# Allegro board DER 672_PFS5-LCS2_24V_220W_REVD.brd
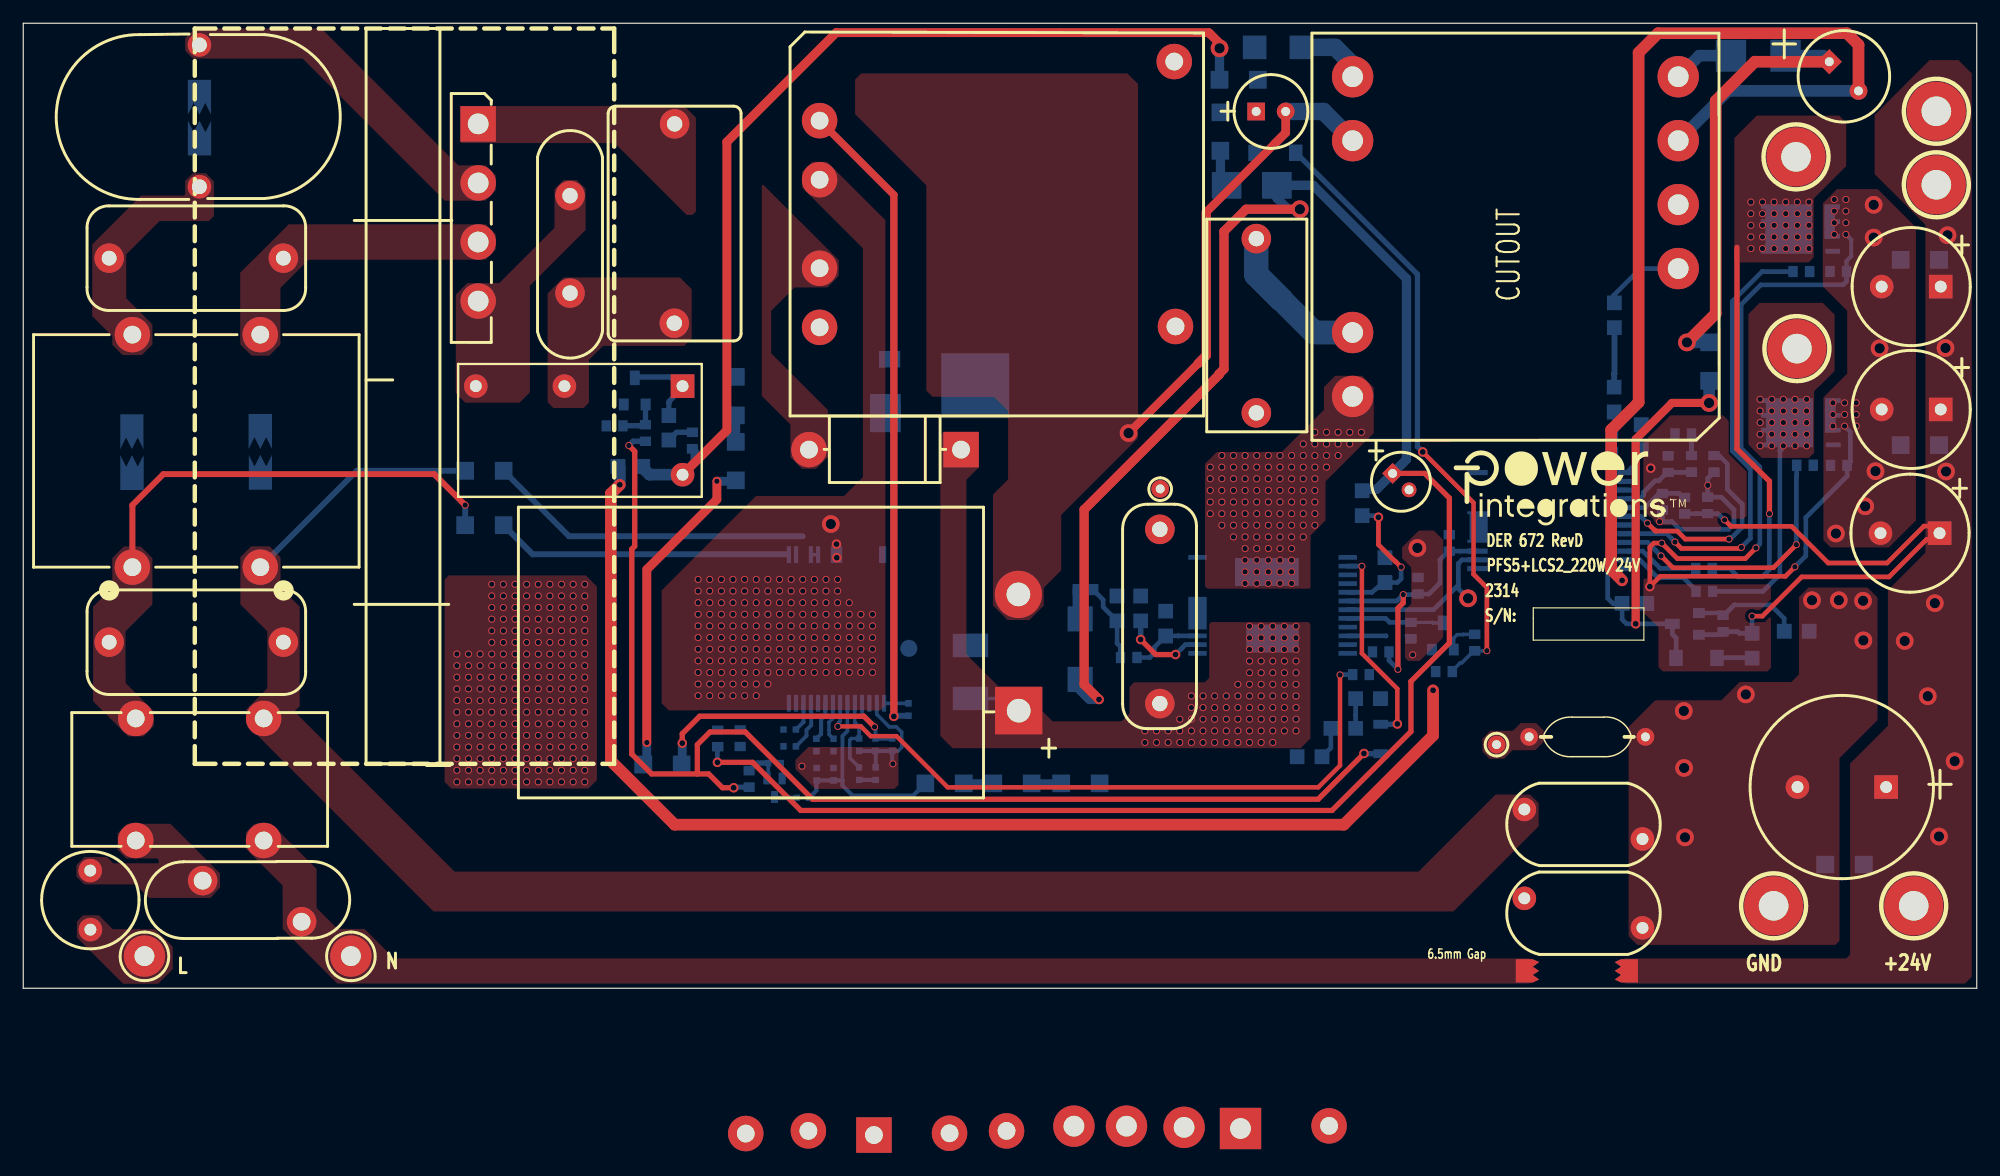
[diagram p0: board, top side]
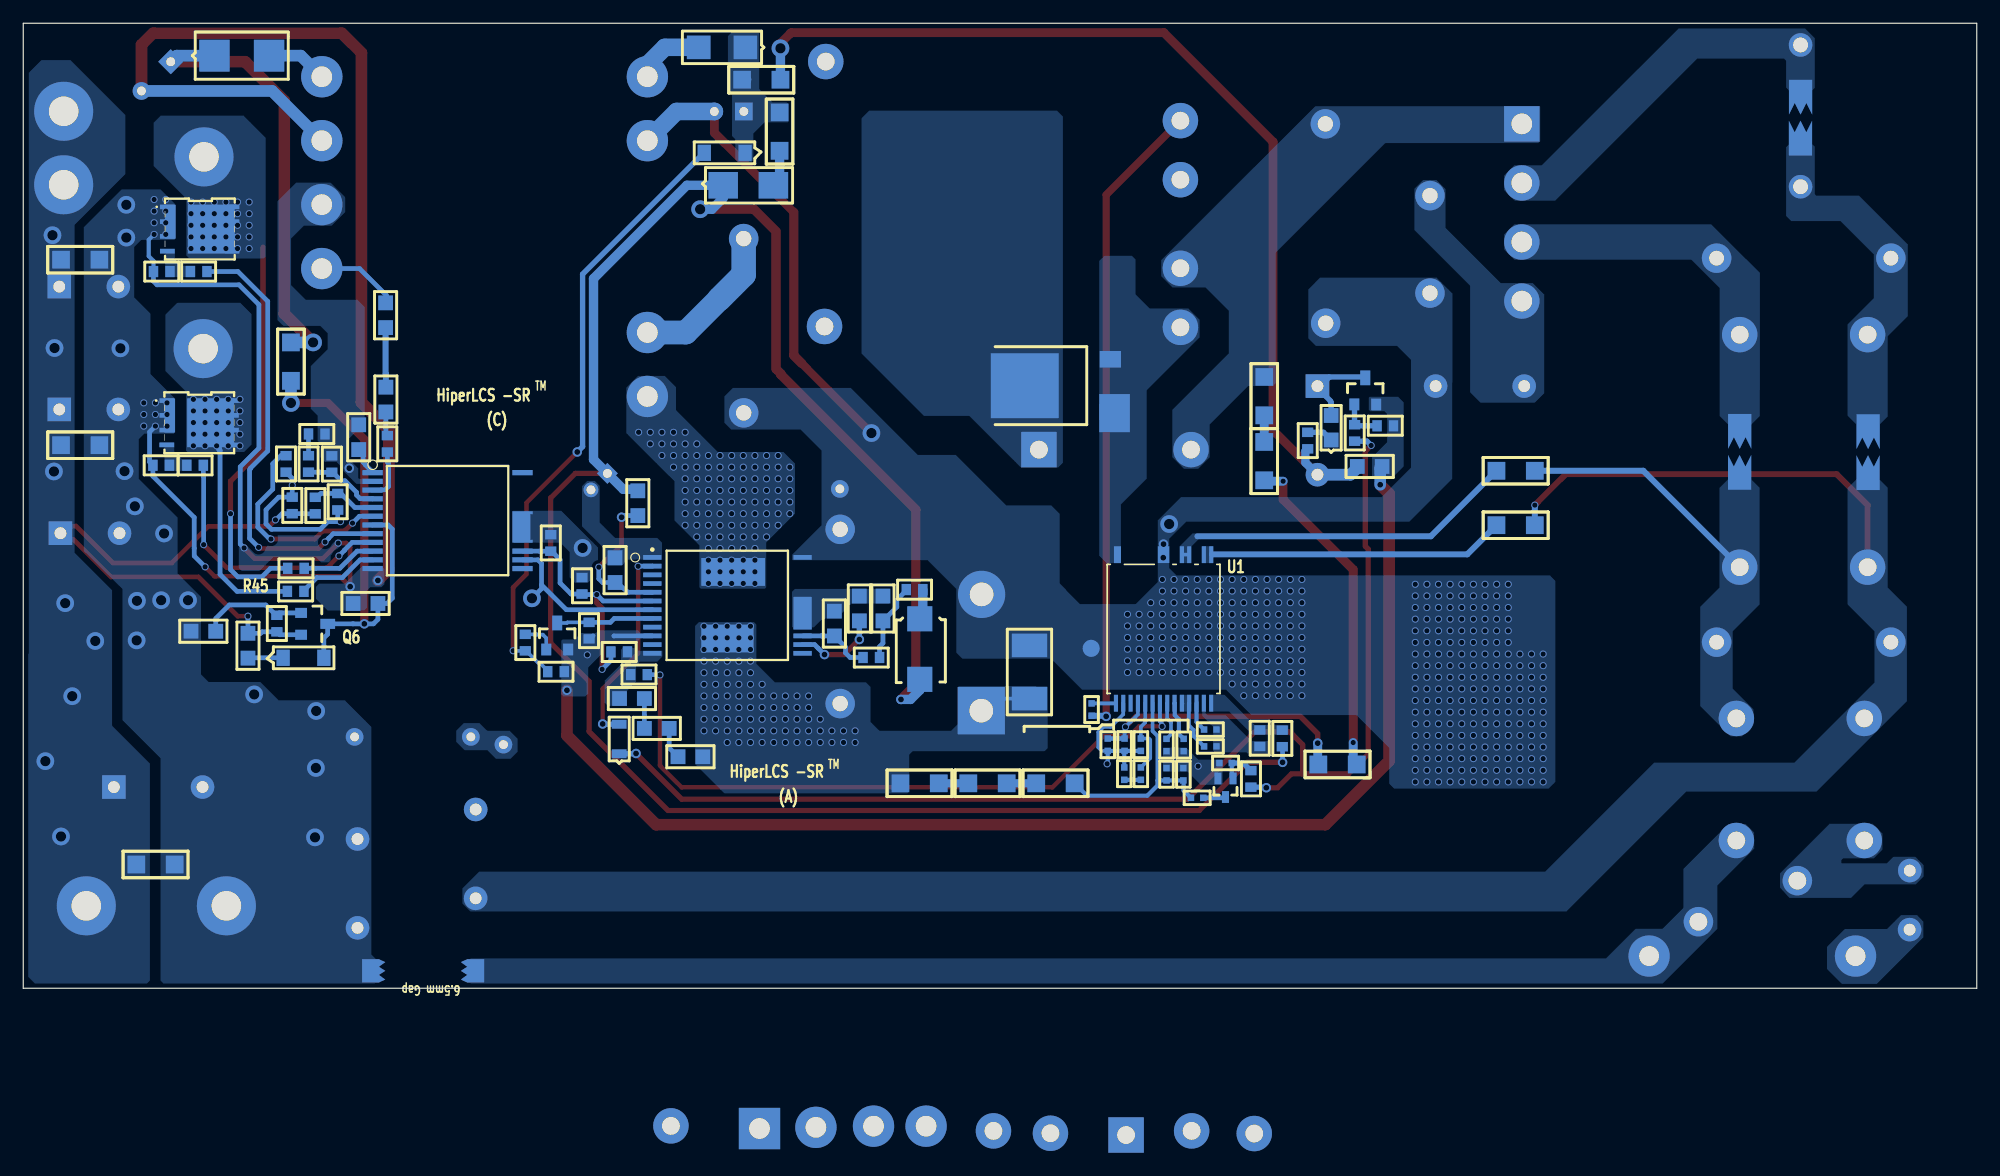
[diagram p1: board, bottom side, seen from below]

Outline 168 x 83 mm; copper layers: TOP, BOTTOM. Coordinates in mm from the lower left corner of the outline.
Outline path: 0,83 168,83 168,0 0,0 0,83

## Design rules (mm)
constraint set DEFAULT: min track width 0.305

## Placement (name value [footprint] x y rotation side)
+24V1  Hole_100mils  [PI_HOLE_100MIL]  162.58 7.09 0 top
BR1  GBU8K-BP  [PIDAXBRIDGEGBU8]  39.12 74.35 270 top
C1  0.33 uF  [PI_NP_CAPRAD709X354LS590D050]  7.39 62.8 0 top
C2  0.33 uF  [PI_NP_CAPRAD709X354LS590D050]  7.39 29.77 0 top
C3  470 nF  [PINPCAPRAD760X450675040]  56.02 74.35 270 top
C5  10 uF  [PISMC0805]  53.28 44.88 180 bottom
C7  1 uF  [PISMC0603]  61.65 22.22 270 bottom
C8  2.2 uF  [PISMC0402]  66.45 22.25 180 bottom
C9  2.2 uF  [PISMC0402]  66.45 20.8 180 bottom
C10  220 uF  [PIPOLCAPCLYD25MM10MMLS080]  85.58 23.88 90 top
C11  10 nF  [PISMC1812]  81.47 24.91 90 bottom
C12  470 pF  [PISMR0402]  74.73 21.48 270 bottom
C14  470 pF  [PISMR0402]  69.68 17.87 90 bottom
C15  100 nF  [PISMR0402]  71.89 21.48 270 bottom
C16  1 uF  [PISMR0402]  73.31 17.93 90 bottom
C17  1 uF  [PISMC0805]  98.24 32.43 270 bottom
C18  10 uF  [PISMC0805]  94.07 31.6 90 bottom
C19  220 nF  [PISMC0805]  96.1 31.6 90 bottom
C20  68 nF  [PINPCAPRAD760X250590040]  97.75 24.48 90 top
C21  47 uF  [PIPOLCAPCLYD200LS80030]  117.76 44.28 315 top
C22  1 uF  [PISMC0805]  117.1 34.9 90 bottom
C23  100 uF  [PIPOLCAPCYLD250LS100030]  106.03 75.41 0 top
C24  1 uF  [PISMC0603]  119.95 33.91 90 bottom
C25  22 nF  [PINPXCAPRAD720X340590040]  106.05 64.48 270 top
C26  3.3 nF  [PINPYCAPRAD540X290LS400040]  129.09 15.38 0 top
C27  330 uF  [PIPOLCAPCYLD400LS200040]  164.9 60.35 180 top
C28  330 uF  [PIPOLCAPCYLD400LS200040]  164.9 49.78 180 top
C29  100 nF  [PISMC0603]  144.87 40.82 90 bottom
C30  10 uF  [PISMC1206]  164.75 46.71 180 bottom
C31  330 uF  [PIPOLCAPCYLD400LS200040]  164.8 39.14 180 top
C32  10 uF  [PISMC1206]  164.75 62.66 180 bottom
C33  10 uF  [PISMC0805]  139.63 33.1 180 bottom
C34  100 uF  [PIPOLCAPCLYD320LS140030]  155.32 79.69 315 top
C35  100 pF  [PISMC0603]  141.46 44.37 90 bottom
C36  2.2 nF  [PISMC0603]  143.47 47.67 180 bottom
C37  470 pF  [PISMC0805]  136.84 56.82 90 bottom
C38  100 nF  [PISMC0603]  122.64 37.59 90 bottom
C39  10 uF  [PISMC0805]  139.15 46.33 90 bottom
C40  2.2 uF  [PISMC0805]  153.58 30.71 180 bottom
C41  3.3 nF  [PINPYCAPRAD540X290LS400040]  129.09 7.74 0 top
C42  150 pF  [PINPCAPRAD6P5X5P5X10MMLSD030]  139.51 21.62 180 top
C43  1800 uF  [PIPOLCAPCLYD630LS300040]  160.2 17.31 180 top
C44  10 uF  [PISMC1206]  158.28 10.65 180 bottom
D1  1N5408G  [PIDV300X200X060DO15D0201AD]  83.95 46.33 180 top
D2  BAS416,115  [PISMDSOD323]  55.52 47.16 90 bottom
D3  VS-5EWH06FNTR-M3  [PI_SM_TO252_DPAK]  74.51 49.61 0 bottom
D4  MURS160T3G  [PISMSMB]  90.9 31.78 270 bottom
D5  ES1A-13-F  [PISMDO214AC12]  107.81 69.06 180 bottom
D6  US1D  [PISMDSMA]  105.9 80.93 0 bottom
D7  B180B-13-F  [PISMDO214AA12]  151.56 80.21 180 bottom
D9  BAV16WS-7-F  [PISMSOD323]  116.75 20.17 90 bottom
F1  5 A  [PI_TR5_SUBMIN_FUSE]  5.78 5.04 90.2 top
FL1  Hole_100mils  [PI_HOLE_100MIL]  152.53 55.02 0 top
FL2  Hole_100mils  [PI_HOLE_100MIL]  152.46 71.51 0 top
FL3  Hole_100mils  [PI_HOLE_100MIL]  164.53 75.43 0 top
FL4  Hole_100mils  [PI_HOLE_100MIL]  164.53 69.11 0 top
FL5  Hole_30mils  [PI_HOLE_30MIL]  97.77 42.95 0 top
FL6  Hole_30mils  [PI_HOLE_30MIL]  126.7 20.95 0 top
GND1  Hole_100mils  [PI_HOLE_100MIL]  150.53 7.09 0 top
L2  20 mH  [PI4P28X19P5X20LSD60]  14.89 46.22 90 top
L3  2.3 mH  [PI4P21P7X11P5D60]  15.17 17.96 90 top
L4  330 uH  [PI_TOROID_2P_550X950_LS480_D050]  15.15 81.13 270 top
LINE  WHT  [PITPKEYSTONE125X125]  10.42 2.77 0 top
NEUTRAL  YEL  [PITPKEYSTONE125X125]  28.18 2.77 0 top
NOREF  -  []  0 0 90 top
NOREF#2  -  []  29.48 19.3 0 top
NOREF#3  -  []  123.02 46.23 0 top
NOREF#4  -  []  0 0 0 top
NOREF#5  -  []  -101.34 71.35 0 top
NOREF#6  -  []  -109.61 -185.23 0 top
Q1  DMN10H700S-7  [PISMSOT23123_1]  51.65 50.22 180 bottom
Q2  RJU003N03T106  [PISMSOT323]  65.26 18.05 0 bottom
Q3  MMBTA06LT1  [PISMSOT23123_1]  121.14 29.13 180 bottom
Q4  AONS66614  [PISMPQFN5X6B]  155.61 67.21 270 bottom
Q5  AONS66614  [PISMPQFN5X6B]  155.66 50.55 270 bottom
Q6  FMMT591  [PISMSOT23123_1]  144.1 30.4 270 bottom
R1  75.0 k  [PISMR1206]  41.31 44.51 180 bottom
R2  75.0 k  [PISMR1206]  41.31 39.83 180 bottom
R3  10  [PISMR0603]  57.54 46.39 90 bottom
R4  10  [PISMR0603]  53.5 47.05 90 bottom
R5  10 k  [PISMR0603]  146.19 32.08 270 bottom
R6  6.2 M  [PISMR1206]  61.27 49.28 90 bottom
R8  6.2 M  [PISMR1206]  61.27 43.69 90 bottom
R9  10  [PISMR0603]  59.73 20.78 90 bottom
R10  10.0 k  [PISMR0402]  76.12 23.44 90 bottom
R11  3.74 M  [PISMR1206]  53.32 19.25 0 bottom
R12  3.74 M  [PISMR1206]  92.57 17.63 180 bottom
R13  6.2 M  [PISMR1206]  86.73 17.63 180 bottom
R14  6.2 M  [PISMR1206]  77.58 17.63 0 bottom
R15  165.0 k  [PISMR0402]  73.29 21.48 270 bottom
R16  280.0 k  [PISMR0402]  69.68 20.39 90 bottom
R17  0.0  [PISMR0402]  68.21 20.39 90 bottom
R18  806.0 k  [PISMR0402]  66.51 16.38 0 bottom
R19  30.1 k  [PISMR0402]  71.89 18.99 270 bottom
R20  196.0 k  [PISMR0402]  68.23 18.94 270 bottom
R21  10  [PISMR0603]  62.42 17.3 90 bottom
R22  10  [PISMR0603]  95.78 28.45 180 bottom
R23  2.2  [PISMR0603]  92.06 34.29 180 bottom
R24  2 M  [PISMR0805]  109.56 19.91 0 bottom
R25  1.8 M  [PISMR0805]  112.45 22.35 0 bottom
R26  200 k  [PISMR0805]  114.59 24.92 0 bottom
R27  22.6 k  [PISMR0603]  114.34 26.97 0 bottom
R28  20 k  [PISMR0603]  117.46 28.93 180 bottom
R30  2.2  [PISMR0805]  115.15 40.65 90 bottom
R31  750  [PISMR1206]  102.96 72.03 90 bottom
R32  47 k  [PISMR0603]  124.83 29.02 90 bottom
R33  158 k  [PISMR0603]  119.34 31.47 270 bottom
R34  100  [PISMR0603]  122.89 27.23 180 bottom
R35  200  [PISMR0805]  148.68 30.53 270 bottom
R36  133 k  [PISMR0603]  142.89 40.8 90 bottom
R37  24.3 k  [PISMR0603]  140.95 42.56 270 bottom
R38  10 k  [PISMR0603]  156.8 61.65 180 bottom
R39  4.7  [PISMR0603]  153.63 61.65 180 bottom
R40  499  [PISMR0603]  145.26 36.12 180 bottom
R41  10  [PISMR1206]  144.98 52.25 90 bottom
R42  10 k  [PISMR0603]  156.85 44.98 180 bottom
R43  4.7  [PISMR0603]  153.93 44.98 180 bottom
R44  150 k  [PISMR0603]  143.47 44.39 90 bottom
R45  499  [PISMR0603]  145.28 34.14 180 bottom
R48  274 k  [PISMR0603]  136.69 47.54 270 bottom
R49  750 k  [PISMR0805]  136.81 49.57 90 bottom
R50  75 k  [PISMR0603]  145.4 45.81 270 bottom
R51  10  [PISMR1206]  106.18 78.14 180 bottom
R53  10 k  [PISMR0603]  50.15 48.38 0 bottom
R54  10 K  [PISMR0402]  64.07 19.37 0 bottom
RL1  SPST NO  [PI_RELAY1]  56.7 51.79 180 top
RT1  10  [PI_RAD770X220LS330D052]  47.02 68.17 270 top
RV1  320 Vac  [PIDISC675X225LS335X140040]  15.43 9.25 0 top
SG1  6.5mm gap  [PI_SPARK_GAP_6P5MM]  133.61 1.5 0 top
SG2  6.5mm gap  [PI_SPARK_GAP_6P5MM]  133.61 1.5 0 bottom
T1  PQ32/20  [PI_BOBBIN_BPQ32_20_12P]  68.49 79.7 0 top
T2  ETD34  [PI_BOBBIN_ETD34_12P_CUTOUT]  142.35 50.88 180 top
U1  PFGCZ  [INSOP-T28F]  69.93 30.9 90 bottom
U2  LCS7265C  [PI_IC_INSOP_24C_1]  107.44 32.93 180 bottom
U3  LSR2000C-H007  [PI_IC_INSOP_24D]  137.95 44.35 180 bottom
VR1  MMSZ5256B-7-F  [PI_SM_SOD-123_12]  105.93 71.86 0 bottom
VR2  MMSZ5245B-7-F  [PI_SM_SOD-123_12]  145.65 28.42 180 bottom

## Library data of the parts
+24V1 FL1-FL4 GND1 = FlyingLead: room: 2
BR1 = DISCRETE BRIDGE_+~~-: alternate symbols: (pidaxbridgegbu8_horz)
C1-C3 C11 C17 C19 C20 C25 C29 C38 C42 = CAP NP
C5 C18 C33 = CAP NP: alternate symbols: (Unisem_RMCF0805UL,CC0805,pismc0805_1)
C7 C35-C37 C40 = CAP NP: room: 2
C8 C9 C12 C14-C16 = CAP NP: alternate symbols: (pismr0402_1); room: 2
C10 = CAP POL: alternate symbols: (pipcap25h40x10mmls080H)
C21 = CAP POL: alternate symbols: (pipolcapclyd200ls80030h)
C22 C24 = CAP NP: room: 1
C23 = CAP POL: alternate symbols: (pipolcapclyd250ls100d30h590)
C26 C41 = CAP NP: alternate symbols: (pinpycaprad540x290ls400040h)
C27 C28 C31 = CAP POL
C30 C32 C44 = CAP NP: alternate symbols: (pismc1206_1)
C34 = CAP POL: alternate symbols: (pipolcapclyd320ls140030430h)
C39 = CAP NP: alternate symbols: (Unisem_RMCF0805UL)
C43 = CAP POL: alternate symbols: (pipolcapclyd630ls3000401000h)
D1 = DIODE: alternate symbols: (pidv300x472x060do14wbead,pidax800x225060do15do201ad,pidv300x200x060do14wbead)
D2 D5 D6 = DIODE
D3 = DIODE_DPAK
D4 D9 = DIODE: room: 1
D7 = DIODE SCHOTTKY
F1 = FUSE
FL5 FL6 = FlyingLead
L2 L3 = TORRID 4P_14_23
L4 = INDUCTOR
LINE NEUTRAL = TESTPOINT
Q1 = FET_N_GSD
Q2 = FET_N_SGD
Q3 = NPN_BEC
Q4 Q5 = FET_N_SGD_123_4_5678
Q6 = PNP_BEC
R1 R2 R22 R23 R30-R32 R34 R39-R41 R43 R45 R51 = R
R3-R6 R8 R9 R11-R21 R36-R38 R42 R44 R48-R50 R53 R54 = R: room: 2
R10 = R: alternate symbols: (pismr0402_1); room: 2
R24 R25 R27 R28 R33 = R: room: 1
R26 = R: alternate symbols: (Unisem_RMCF0805UL)
R35 = R: alternate symbols: (pismr0805_1)
RL1 = RELAY SPST_NO_1634
RT1 = THERMISTOR
RV1 = VARISTOR
SG1 SG2 = SPARK_GAP
T1 = BPQ32/20_12P/GENERIC
T2 = BETD34_12P/GENERIC
U1 = PFSGaN_InSOP-T28F28: User Part Number: PN; Tolerance: TOL
U2 = HiperLCS-SR_A_INSOP24C_5
U3 = HiperLCS2-SR
VR1 VR2 = DIODE_ZENER

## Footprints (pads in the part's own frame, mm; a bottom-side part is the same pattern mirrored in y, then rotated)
INSOP-T28F
  rect 1.448x0.356 smd: 1(-6.388,4.095) 2(-6.388,3.465) 3(-6.388,2.835) 4(-6.388,2.205) 5(-6.388,1.575) 6(-6.388,0.945) 7(-6.388,0.315) 8(-6.388,-0.315) 9(-6.388,-0.945) 10(-6.388,-1.575) 11(-6.388,-2.205) 12(-6.388,-2.835) 13(-6.388,-3.465) 14(-6.388,-4.095) 15(6.388,-4.095) 16(6.388,-3.465) 18(6.388,-2.205) 19(6.388,-1.575)
  rect 1.448x0.986 smd: 21(6.388,0)
  rect 1.448x0.61 smd: 28(6.388,3.968)
PI4P21P7X11P5D60
  round 3.048 hole 1.524: 1(-5.25,5.5) 2(-5.25,-5.5) 3(5.25,-5.5) 4(5.25,5.5)
PI4P28X19P5X20LSD60
  round 3.048 hole 1.524: 1(-10,-5.5) 2(-10,5.5) 3(10,5.5) 4(10,-5.5)
PI_BOBBIN_BPQ32_20_12P
  rect 3.048x3.048 hole 1.524: 1(4.674,-92.329)
  round 3.048 hole 1.524: 2(0,-5.08) 3(0,-10.16) 4(0,-17.78) 5(0,-22.86) 6(-0.965,-91.973) 7(-6.35,-92.202) 8(30.607,-22.784) 9(11.176,-92.177) 10(16.078,-91.973) 11(43.815,-91.542) 12(30.5,0)
PI_BOBBIN_ETD34_12P_CUTOUT
  rect 3.556x3.556 hole 1.778: 1(37.668,62.941)
  round 3.556 hole 1.778: 2(42.52,62.84) 3(0.025,-11.025) 4(0.025,-16.525) 5(0.025,-22.025) 6(0.025,-27.525) 7(28.025,-27.525) 8(28.025,-22.025) 9(51.994,62.738) 10(47.473,62.738) 11(28.025,-5.525) 12(28.025,-0.025)
PI_HOLE_30MIL
  round 1.524 hole 0.762: 1(0,0)
PI_HOLE_100MIL
  round 5.08 hole 2.54: 1(0,0)
PI_IC_INSOP_24C_1
  rect 1.58x0.41 smd: 1(-6.46,4.125) 2(-6.46,3.375) 3(-6.46,2.625) 4(-6.46,1.875) 5(-6.46,1.125) 6(-6.46,0.375) 7(-6.46,-0.375) 8(-6.46,-1.125) 9(-6.46,-1.875) 10(-6.46,-2.625) 11(-6.46,-3.375) 12(-6.46,-4.125) 13(6.46,-4.125) 14(6.46,-3.375) 15(6.46,-2.625) 24(6.46,4.125)
  rect 1.58x2.81 smd: 16(6.46,-0.675)
  rect 5.49x2.4 smd: 19(0.495,2.875)
  rect 4.5x2.4 smd: 25(0,-2.85)
PI_IC_INSOP_24D
  rect 1.75x0.45 smd: 1(0,0) 2(0,-0.75) 3(0,-1.5) 4(0,-2.25) 5(0,-3) 6(0,-3.75) 7(0,-4.5) 8(0,-5.25) 9(0,-6) 10(0,-6.75) 11(0,-7.5) 12(0,-8.25) 13(12.89,-8.25) 14(12.89,-7.5) 15(12.89,-6.75) 24(12.89,0)
  custom 0.438x0.438 smd: 16(12.89,-4.67)
PI_NP_CAPRAD709X354LS590D050
  round 2.54 hole 1.27: 1(0,0) 2(14.986,0)
PI_RAD770X220LS330D052
  round 2.54 hole 1.321: 1(0,0) 2(8.382,0)
PI_RELAY1
  rect 2.032x2.032 hole 1.016: 1(0,0)
  round 2.032 hole 1.016: 3(10.16,0) 4(17.78,0) 6(0,7.62)
PI_SM_SOD-123_12
  rect 1.143x1.397 smd: 1(0,0) 2(3.505,0)
PI_SM_TO252_DPAK
  rect 1.829x1.422 smd: 1(0,0) 3(0,-4.445)
  rect 5.842x5.588 smd: 2(7.62,-2.223)
PI_SPARK_GAP_6P5MM
  custom 0.5x0.5 smd: 1(-4.25,0) 2(4.25,0)
PI_TOROID_2P_550X950_LS480_D050
  round 2.032 hole 1.27: 1(0,0) 2(12.192,0)
PI_TR5_SUBMIN_FUSE
  round 2.032 hole 1.016: 1(0,0) 2(5.08,0)
PIDAXBRIDGEGBU8
  rect 3.048x3.048 hole 1.778: 1(0,0)
  round 3.048 hole 1.778: 2(5.08,0) 3(10.16,0) 4(15.24,0)
PIDISC675X225LS335X140040
  round 2.54 hole 1.524: 1(0,0) 2(8.509,-3.531)
PIDV300X200X060DO15D0201AD
  rect 3.048x3.048 hole 1.524: 1(3.302,0)
  round 3.048 hole 1.524: 2(16.383,0)
PINPCAPRAD6P5X5P5X10MMLSD030
  round 1.524 hole 0.762: 1(0,0) 2(10,0)
PINPCAPRAD760X250590040
  round 2.54 hole 1.321: 1(0,0) 2(14.986,0)
PINPCAPRAD760X450675040
  round 2.54 hole 1.321: 1(0,0) 2(17.145,-0.025)
PINPXCAPRAD720X340590040
  round 2.54 hole 1.321: 1(0,0) 2(14.986,0)
PINPYCAPRAD540X290LS400040
  round 2.032 hole 1.016: 1(0,0) 2(10.16,-2.54)
PIPOLCAPCLYD25MM10MMLS080
  rect 4.064x4.064 hole 2.032: 1(0,-0.025)
  round 4.064 hole 2.032: 2(10,0)
PIPOLCAPCLYD200LS80030
  rect 1.27x1.27 hole 0.762: 1(0,0)
  round 1.27 hole 0.762: 2(2,0)
PIPOLCAPCLYD320LS140030
  rect 1.524x1.524 hole 0.762: 1(0,0)
  round 1.524 hole 0.762: 2(3.556,0)
PIPOLCAPCLYD630LS300040
  rect 2.032x2.032 hole 1.016: 1(0,0)
  round 2.032 hole 1.016: 2(7.62,0)
PIPOLCAPCYLD250LS100030
  rect 1.524x1.524 hole 0.762: 1(0,0)
  round 1.524 hole 0.762: 2(2.54,0)
PIPOLCAPCYLD400LS200040
  rect 2.032x2.032 hole 1.016: 1(0,0)
  round 2.032 hole 1.016: 2(5.08,0)
PISMC0402
  rect 0.559x0.559 smd: 1(0,0) 2(1.067,0)
PISMC0603
  rect 0.813x0.965 smd: 1(0,0) 2(1.422,0)
PISMC0805
  rect 1.27x1.27 smd: 1(0,0) 2(2.134,0)
PISMC1206
  rect 1.524x1.524 smd: 1(0,0) 2(3.302,0)
PISMC1812
  rect 2.032x3.048 smd: 1(0,0) 2(4.572,0)
PISMDO214AA12
  rect 2.616x2.743 smd: 1(0,0) 2(4.699,0)
PISMDO214AC12
  rect 2.54x2.286 smd: 1(0,0) 2(4.318,0)
PISMDSMA
  rect 2.032x2.032 smd: 1(0,0) 2(4.013,0)
PISMDSOD323
  rect 1.27x1.27 smd: 1(0,0) 2(2.108,0)
PISMPQFN5X6B
  rect 0.406x1.27 smd: 1(0,0) 2(1.27,0) 3(2.54,0) 4(3.81,0)
  rect 0.406x1.219 smd: 5(3.81,5.588) 6(2.54,5.588) 7(1.27,5.588) 8(0,5.588)
PISMR0402
  rect 0.559x0.559 smd: 1(0,0) 2(1.067,0)
PISMR0603
  rect 0.813x0.965 smd: 1(0,0) 2(1.422,0)
PISMR0805
  rect 1.27x1.27 smd: 1(0,0) 2(2.134,0)
PISMR1206
  rect 1.524x1.524 smd: 1(0,0) 2(3.302,0)
PISMSMB
  rect 2.159x2.159 smd: 1(0,0) 2(5.207,0)
PISMSOD323
  rect 0.762x1.27 smd: 1(0,0) 2(2.54,0)
PISMSOT323
  rect 0.61x1.016 smd: 1(0,0) 2(-1.3,0) 3(-0.65,1.6)
PISMSOT23123_1
  rect 0.864x1.016 smd: 1(-1.88,0) 2(0,0)
  rect 0.864x1.27 smd: 3(-0.94,2.286)
PITPKEYSTONE125X125
  round 3.556 hole 1.702: 1(0,0)

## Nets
5VL: C24.1 C38.1 R28.1 U2.6 U3.15
+24V: +24V1.1 C27.1 C28.1 C29.1 C30.1 C31.1 C32.1 C43.1 C44.1 FL3.1 FL4.1 Q6.2(EMITTER) R5.2 R35.1 R36.1 SG1.2
GND: C26.2 C27.2 C28.2 C30.2 C31.2 C32.2 C33.1 C34.2 C40.1 C41.2 C42.1 C43.2 C44.2 GND1.1 Q4.1 Q4.2 Q4.3(S3) Q5.1 Q5.2 Q5.3(S3) R38.1 R42.1 SG2.2 T2.5 U3.12
VCC: C7.1 R9.2 U1.14
BM: D9.1 R4.1 R21.1
BPS: D7.2 T2.6
C: C15.1 R19.1 U1.5
D1: R2.1 U1.15 U1.16
D2: R1.1 U1.18 U1.19
FB: C14.1 R14.1 R18.2 R20.2 U1.6
FL: U2.7 U3.14
G2: C7.2 C8.2 C9.2 U1.13
GP: C5.2 C24.2 C38.2 Q1.2(S) Q3.2(EMITTER) R33.2 R34.2 R53.1 U2.10 U3.16
GSB: C29.2 C35.2 C36.2 C39.2 R37.2 R50.2 T2.4 U3.2
IS: C37.2 T2.3
L: D3.3 T1.5 U1.28
LINE1: F1.2 L3.1 RV1.1
NEUTRAL1: L3.2 NEUTRAL.1 RV1.2 SG1.1 SG2.1
OVP: R32.1 R34.1 VR1.2
PFC_VCC: C21.1 D4.2 D5.1 R9.1 R30.2
PGOOD: R27.1 U1.7
PGT: R16.2 U1.8
PS: R17.2 U1.9
REF: C9.1 U1.10 U1.11
RELAY_VCC: C5.1 R3.1 R51.2 RL1.6
RTN: C3.2 C10.2 C11.2 C20.2 C23.2 C25.2 FL5.1 RL1.3 RT1.2 T1.3 T2.8 U1.21 U2.24
TO: U1.3
V: C12.1 R11.2 R15.1 U1.4
VBULK: C10.1 C11.1 C20.1 D1.1 D3.2 R12.1 R24.1 U2.25
VDR: C8.1 U1.12
VRECT: BR1.1 C3.1 D1.2 R6.2 T1.4
VS: R10.1 T1.2
VSC: R10.2 U1.1
Y1: C2.2 C26.1 L2.1 L3.3 R1.2
Y2: C2.1 C41.1 L2.2 L3.4 R2.2
N4285050: C17.1 C18.2 C19.2 U2.16
N4286456: C19.1 U2.14
N4286477: C17.2 R22.1 U2.15
N4286493: D4.1 R23.2
N4298336: D6.2 T2.7
N4342721: C23.1 D6.1 R31.2 R51.1 VR1.1
N4344251: Q3.3 R33.1 U2.8
N4345605: C21.2 C22.2 U2.1
N4347891: C22.1 R30.1 U2.5
N4369156: R36.2 R37.1 U3.5
N4369530: C35.1 R44.1 U3.4
N4369660: R48.2 U3.3
N4369788: C39.1 U3.1
N4383576: R43.2 U3.9
N4398139: FL2.1 Q4.5 Q4.6 Q4.7 Q4.8 R40.1
N4399978: FL1.1 Q5.5 Q5.6 Q5.7 Q5.8 R45.1
N4403558: Q4.4 R38.2 R39.1
N4403571: R39.2 U3.8
N4411199: R48.1 R49.1
N4411203: C37.1 R49.2
N4415619: C36.1 R44.2
N4433947: Q5.4 R42.2 R43.1
N4462598: C33.2 Q6.3 R41.1 U3.7 VR2.2
N4490514: C25.1 T2.11
N4535120: R26.2 R27.2 R28.2 U2.12
N4541248: U2.3
N11926581: R50.1 U3.6(PS)
N12003586: Q3.1 R32.2
N12130188: R45.2 U3.11
N12130239: R40.2 U3.10
N12141521: T2.12 U2.19
N12150808: C18.1 R22.2 R23.1
N12190763: C34.1 D7.1 R41.2
N12204254: C1.1 L2.3 L4.2
N12204278: BR1.2 L4.1
N12204372: BR1.4 RL1.4(NO) RT1.1
N12204532: BR1.3(AC2) C1.2 L2.4
N12221428: R6.1 R8.2
N12221554: R8.1 R11.1
N12221692: R12.2 R13.1
N12221812: R13.2 R14.2
N12221868: C12.2 C14.2 C15.2 C16.2 Q2.1(S) R15.2 R16.1 R17.1 R20.1 R54.2 U1.2
N12222300: C16.1 R19.2
N12229995: D5.2 R31.1
N12233962: Q2.3 R18.1
N12234276: Q2.2 R21.2 R54.1
N12240068: Q1.1 R4.2 R53.2
N12240080: D2.2 Q1.3 RL1.1
N12240868: D2.1 R3.2
N12267959: C40.2 Q6.1 R5.1
N12332190: R24.2 R25.1
N12332212: R25.2 R26.1
N12355111: R35.2 VR2.1
N12387180: F1.1 LINE.1
N12418022: D9.2 U2.2
N12539062: C42.2 FL6.1

Pads without a net: D3 1; T1 1 6 7 8 9 10 11 12; T2 1 2 9 10; U2 4 9 11 13; U3 13 24

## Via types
v1: diameter 0.813, hole 0.508, TOP to BOTTOM, 19 vias
v2: diameter 1.524, hole 0.889, TOP to BOTTOM, 30 vias
v3: diameter 0.61, hole 0.457, TOP to BOTTOM, 644 vias

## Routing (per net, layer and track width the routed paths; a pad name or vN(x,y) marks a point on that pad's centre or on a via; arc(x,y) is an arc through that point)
5VL: length 22.5
  TOP w0.45: v3(118.68,33.86) 118.68,33.15 118.22,32.69 v3(118.22,27.43)
  BOTTOM w0.4: R28.1 117.46,28.19 v3(118.22,27.43) ; U3.15 123.61,37.6 123.6,37.59 C38.1 122.56,37.59 121.83,36.86 121.83,34.86 120.88,33.91 C24.1 119.9,33.86 v3(118.68,33.86) 118.13,33.31 U2.6
+24V: length 48.7
  TOP w0.4: v3(146.31,40.28) 146.87,39.73 152.08,39.73 155.23,36.58 160.28,36.58 163.46,39.75 164.07,39.75 ; 164.14,38.61 163.69,38.61 160.46,35.38 152.94,35.38 149.56,32 v3(148.68,32)
  BOTTOM w0.4: R36.1 143.82,40.8 143.84,40.82 C29.1 145.74,40.82 146.27,40.28 v3(146.31,40.28) ; v3(148.68,32) R35.1 147.59,30.53 147.46,30.66 R5.2 145.93,30.4 Q6.2
  vias: v2(161.81,29.87) v2(163.79,25.12) v2(164.4,33.12) v2(164.75,13.05) v2(165.31,55.07) v2(165.36,44.45) v2(165.49,64.77) v2(166.1,19.53)
GND: length 165.6
  TOP w0.4: v3(149.01,37.87) 148.09,36.96 142.25,36.96 v3(140.92,38.29) 140.23,38.29 139.89,37.94 v1(139.89,34.54) 140.78,35.43 151.55,35.43 v3(152.36,36.25)
  TOP w0.762: C28.2 159.44,49.4
  TOP w1: v1(137.5,35.08) 136.56,36.02 136.56,48.03 138.92,50.39 138.92,80.47 140.6,82.14 156.83,82.14 157.83,81.14 C34.2
  BOTTOM w0.35: R38.1 156.8,62.56 157.21,62.97 157.21,64.38 v3(156.75,64.84)
  BOTTOM w0.4: v3(149.01,37.87) 149.34,38.2 149.34,44.85 147.74,46.45 147.74,58.8 149.44,60.5 156.49,60.5 156.8,60.81 R38.1 ; v3(152.36,36.25) 153.3,37.18 153.3,37.84 153.3,37.85 153.3,40.49 156.85,44.05 R42.1 157.13,45.26 157.13,47.85 v3(156.64,48.35)
  BOTTOM w1: C34.2 146.6,77.18 T2.5
  vias: v2(142.81,23.85) v2(142.83,18.95) v2(142.91,12.98) v2(148.14,25.27) v2(153.83,33.37) v2(155.89,39.12) v2(156.14,33.37) v2(158.22,33.32) v2(158.25,29.92) v2(158.4,41.45) v2(159.14,67.39) v2(159.14,64.57) v2(159.29,44.47) v2(159.65,55.04) v3(155.64,50.35) v3(155.64,49.35) v3(155.64,48.35) v3(155.75,67.84) v3(155.75,66.84) v3(155.75,65.84) v3(155.75,64.84) v3(156.64,50.35) v3(156.64,49.35) v3(156.75,67.84) v3(156.75,66.84) v3(156.75,65.84) v3(157.64,50.35) v3(157.64,49.35) v3(157.64,48.35)
BM: length 105.5
  TOP w0.45: 57.97,18.43 58.94,18.43 60.13,17.25 v1(61.1,17.25) ; 57.97,18.43 54.04,18.43 52.33,20.14 ; 57.97,18.43 57.97,20.95 59.06,22.05 62.09,22.05 67.88,16.26 111.36,16.26 v1(115.3,20.19)
  TOP w0.457: 52.33,20.14 52.33,37.77 52.58,38.02 52.58,46.18 v3(52.08,46.68)
  BOTTOM w0.45: R21.1 61.15,17.3 v1(61.1,17.25) ; v1(115.3,20.19) 115.33,20.17 D9.1
  BOTTOM w0.46: v3(52.08,46.68) 52.45,47.05 R4.1
BPS: length 5.3
  BOTTOM w1: T2.6 144.14,80.21 D7.2
C: length 6.8
  BOTTOM w0.305: R19.1 71.08,19.8 71.08,21.36 71.2,21.48 C15.1 71.89,22.48 71.51,22.86 U1.5
D1: length 25.5
  BOTTOM w0.508: R2.1 43.81,37.32 65.77,37.32
D2: length 28.7
  BOTTOM w0.305: U1.18 U1.19
  BOTTOM w0.508: 67.03,38.87 46.94,38.87 R1.1
FB: length 19.2
  BOTTOM w0.305: 70.88,22.12 U1.6
  BOTTOM w0.33: 70.45,17.87 70.45,17.88 70.45,21.7 70.88,22.12
  BOTTOM w0.35: R14.1 76.52,16.56 71.33,16.56 70.45,17.44 70.45,17.87 C14.1 68.28,17.87
  BOTTOM w0.356: R20.2 68.28,17.87 68.21,17.8 68.21,17.01 R18.2
FL: length 15.5
  BOTTOM w0.4: 123.43,34.7 123.43,34.37 v2(124.25,33.54) ; 123.43,34.7 123.43,36.54 123.74,36.85 U3.14 ; 123.43,34.7 121.29,32.56 U2.7
GP: length 109.9
  TOP w1: v1(51.3,43.31) 50.53,42.54 50.53,19.55 56.02,14.07 113.57,14.07 121.24,21.74 v1(121.24,25.63)
  BOTTOM w0.305: 121.12,29.11 Q3.2 121.32,29.13 121.35,29.16
  BOTTOM w0.4: 117.21,30.3 117.2,30.31 U2.10 ; 118.99,30.31 119.31,29.99
  BOTTOM w1: 51.24,44.61 51.24,44.78 ; 51.24,44.78 51.3,44.72 v1(51.3,43.31) ; 51.24,44.78 C5.2
  vias: v2(119.89,37.87) v3(119.49,28.68)
GSB: length 14.3
  BOTTOM w0.4: 141.03,41.14 R37.2 140.95,40.36 v3(140.73,40.13) 141.8,40.13 142.46,39.47 146.65,39.47 147.12,39.95 147.12,41.15 146.03,42.24 C29.2 v3(144.87,43.26) 144.87,43.85 R50.2 145.4,44.37 145.41,44.36
  vias: v1(139.96,44.73)
IS: length 7.2
  BOTTOM w0.4: T2.3 139.08,61.9 136.76,59.58 136.76,59.03 C37.2
OVP: length 53.4
  TOP w0.381: v1(120.35,46.13) 124.72,41.76 124.72,35.61
  TOP w0.4: 124.72,35.61 125.87,34.46 v3(125.87,29.03)
  BOTTOM w0.305: v3(125.87,29.03) 125.86,29.02 R32.1 124.75,29.02 123.73,28 123.59,28 122.89,27.3 R34.1
  BOTTOM w0.457: VR1.2 109.48,71.81 109.51,71.81 119.9,61.42 119.9,46.58 v1(120.35,46.13)
PFC_VCC: length 187.1
  TOP w0.45: v1(59.7,19.43) 62.72,19.43 66.86,15.29 112.56,15.29 119.34,22.07 119.34,26.39 122.64,29.7 122.64,42.16 120.52,44.28 C21.1
  TOP w0.8: v2(109.79,67) 105.17,67 103.26,65.1 103.26,53.26 102.84,52.84 102.84,52.77 91.24,41.17 91.24,26.12 v1(92.52,24.84)
  BOTTOM w0.4: v1(59.7,19.43) 59.7,20.75 R9.1
  BOTTOM w0.8: v2(109.79,67) 108.77,67 107.81,67.97 D5.1 110.93,69.06 118.96,61.04 118.96,45.47 C21.1 116.4,42.91 115.27,42.91 R30.2 ; D4.2 90.9,25.64 91.7,24.84 v1(92.52,24.84)
PGOOD: length 57.1
  TOP w0.381: v3(113.24,26.95) 113.24,19.15 111.37,17.28 79.5,17.28 75.1,21.68 72.88,21.68 72.04,22.52 v3(70.06,22.52)
  BOTTOM w0.33: v3(70.06,22.52) 70.11,22.58 70.11,22.82 70.25,22.95 U1.7
  BOTTOM w0.4: R27.1 113.27,26.97
  BOTTOM w0.45: 113.27,26.97 v3(113.24,26.95)
PGT: length 3.4
  BOTTOM w0.305: R16.2 69.3,21.84 69.3,22.21 69.3,22.88 69.63,23.21 69.63,24.51 U1.8
PS: length 3.4
  BOTTOM w0.305: 69.01,24.5 U1.9
  BOTTOM w0.35: R17.2 68.62,21.87 68.62,23.14 68.97,23.49 68.97,24.52 U1.9 68.99,24.51
REF: length 4.3
  BOTTOM w0.33: C9.1 67.36,21.71 67.36,22.21 67.76,22.61 67.76,24.48 U1.11 ; 68.33,24.48 U1.10
RELAY_VCC: length 86.5
  TOP w0.762: RL1.6 60.51,47.98 60.51,72.8 69.91,82.19 101.94,82.19 102,82.13 102.02,82.13 102.88,81.27 v2(102.88,80.85)
  BOTTOM w0.7: R3.1 57.74,46.2 57.74,45.21 RL1.6
  BOTTOM w0.8: v2(102.88,80.85) 102.88,78.15 R51.2
  BOTTOM w1: C5.1 53.38,44.78 53.38,44.65 53.86,44.17 RL1.6
RTN: length 40.1
  TOP w0.7: 107.63,72.64 101.74,66.75 ; 101.04,53.73 v2(95.06,47.75)
  TOP w0.75: C23.2 108.57,73.58 107.63,72.64
  TOP w0.8: 101.04,53.73 101.74,54.43 101.74,66.75
  BOTTOM w1.5: T2.8 111.81,75.41 C23.2
  vias: v1(69.94,38.2) v1(69.96,37.03) v2(69.45,39.93) v3(37.29,28.75) v3(37.29,27.75) v3(37.29,26.75) v3(37.29,25.75) v3(37.29,24.75) v3(37.29,23.75) v3(37.29,22.75) v3(37.29,21.75) v3(37.29,20.75) v3(37.29,19.75) v3(37.29,18.75) v3(37.29,17.75) v3(38.29,28.75) v3(38.29,27.75) v3(38.29,26.75) v3(38.29,25.75) v3(38.29,24.75) v3(38.29,23.75) v3(38.29,22.75) v3(38.29,21.75) v3(38.29,20.75) v3(38.29,19.75) v3(38.29,18.75) v3(38.29,17.75) v3(39.29,28.75) v3(39.29,27.75) v3(39.29,26.75) v3(39.29,25.75) v3(39.29,24.75) v3(39.29,23.75) v3(39.29,22.75) v3(39.29,21.75) v3(39.29,20.75) v3(39.29,19.75) v3(39.29,18.75) v3(39.29,17.75) v3(40.29,34.75) v3(40.29,33.75) v3(40.29,32.75) v3(40.29,31.75) v3(40.29,30.75) v3(40.29,29.75) v3(40.29,28.75) v3(40.29,27.75) v3(40.29,26.75) v3(40.29,25.75) v3(40.29,24.75) v3(40.29,23.75) v3(40.29,22.75) v3(40.29,21.75) v3(40.29,20.75) v3(40.29,19.75) v3(40.29,18.75) v3(40.29,17.75) v3(41.29,34.75) v3(41.29,33.75) v3(41.29,32.75) v3(41.29,31.75) v3(41.29,30.75) v3(41.29,29.75) v3(41.29,28.75) v3(41.29,27.75) v3(41.29,26.75) v3(41.29,25.75) v3(41.29,24.75) v3(41.29,23.75) v3(41.29,22.75) v3(41.29,21.75) v3(41.29,20.75) v3(41.29,19.75) v3(41.29,18.75) v3(41.29,17.75) v3(42.29,34.75) v3(42.29,33.75) v3(42.29,32.75) v3(42.29,31.75) v3(42.29,30.75) v3(42.29,29.75) v3(42.29,28.75) v3(42.29,27.75) v3(42.29,26.75) v3(42.29,25.75) v3(42.29,24.75) v3(42.29,23.75) v3(42.29,22.75) v3(42.29,21.75) v3(42.29,20.75) v3(42.29,19.75) v3(42.29,18.75) v3(42.29,17.75) v3(43.29,34.75) v3(43.29,33.75) v3(43.29,32.75) v3(43.29,31.75) v3(43.29,30.75) v3(43.29,29.75) v3(43.29,28.75) v3(43.29,27.75) v3(43.29,26.75) v3(43.29,25.75) v3(43.29,24.75) v3(43.29,23.75) v3(43.29,22.75) v3(43.29,21.75) v3(43.29,20.75) v3(43.29,19.75) v3(43.29,18.75) v3(43.29,17.75) v3(44.29,34.75) v3(44.29,33.75) v3(44.29,32.75) v3(44.29,31.75) v3(44.29,30.75) v3(44.29,29.75) v3(44.29,28.75) v3(44.29,27.75) v3(44.29,26.75) v3(44.29,25.75) v3(44.29,24.75) v3(44.29,23.75) v3(44.29,22.75) v3(44.29,21.75) v3(44.29,20.75) v3(44.29,19.75) v3(44.29,18.75) v3(44.29,17.75) v3(45.29,34.75) v3(45.29,33.75) v3(45.29,32.75) v3(45.29,31.75) v3(45.29,30.75) v3(45.29,29.75) v3(45.29,28.75) v3(45.29,27.75) v3(45.29,26.75) v3(45.29,25.75) v3(45.29,24.75) v3(45.29,23.75) v3(45.29,22.75) v3(45.29,21.75) v3(45.29,20.75) v3(45.29,19.75) v3(45.29,18.75) v3(45.29,17.75) v3(46.29,34.75) v3(46.29,33.75) v3(46.29,32.75) v3(46.29,31.75) v3(46.29,30.75) v3(46.29,29.75) v3(46.29,28.75) v3(46.29,27.75) v3(46.29,26.75) v3(46.29,25.75) v3(46.29,24.75) v3(46.29,23.75) v3(46.29,22.75) v3(46.29,21.75) v3(46.29,20.75) v3(46.29,19.75) v3(46.29,18.75) v3(46.29,17.75) v3(47.29,34.75) v3(47.29,33.75) v3(47.29,32.75) v3(47.29,31.75) v3(47.29,30.75) v3(47.29,29.75) v3(47.29,28.75) v3(47.29,27.75) v3(47.29,26.75) v3(47.29,25.75) v3(47.29,24.75) v3(47.29,23.75) v3(47.29,22.75) v3(47.29,21.75) v3(47.29,20.75) v3(47.29,19.75) v3(47.29,18.75) v3(47.29,17.75) v3(48.29,34.75) v3(48.29,33.75) v3(48.29,32.75) v3(48.29,31.75) v3(48.29,30.75) v3(48.29,29.75) v3(48.29,28.75) v3(48.29,27.75) v3(48.29,26.75) v3(48.29,25.75) v3(48.29,24.75) v3(48.29,23.75) v3(48.29,22.75) v3(48.29,21.75) v3(48.29,20.75) v3(48.29,19.75) v3(48.29,18.75) v3(48.29,17.75) v3(58.04,35.16) v3(58.04,34.16) v3(58.04,33.16) v3(58.04,32.16) v3(58.04,31.16) v3(58.04,30.16) v3(58.04,29.16) v3(58.04,28.16) v3(58.04,27.16) v3(58.04,26.16) v3(58.04,25.16) v3(59.04,35.16) v3(59.04,34.16) v3(59.04,33.16) v3(59.04,32.16) v3(59.04,31.16) v3(59.04,30.16) v3(59.04,29.16) v3(59.04,28.16) v3(59.04,27.16) v3(59.04,26.16) v3(59.04,25.16) v3(60.04,35.16) v3(60.04,34.16) v3(60.04,33.16) v3(60.04,32.16) v3(60.04,31.16) v3(60.04,30.16) v3(60.04,29.16) v3(60.04,28.16) v3(60.04,27.16) v3(60.04,26.16) v3(60.04,25.16) v3(61.04,35.16) v3(61.04,34.16) v3(61.04,33.16) v3(61.04,32.16) v3(61.04,31.16) v3(61.04,30.16) v3(61.04,29.16) v3(61.04,28.16) v3(61.04,27.16) v3(61.04,26.16) v3(61.04,25.16) v3(62.04,35.16) v3(62.04,34.16) v3(62.04,33.16) v3(62.04,32.16) v3(62.04,31.16) v3(62.04,30.16) v3(62.04,29.16) v3(62.04,28.16) v3(62.04,27.16) v3(62.04,26.16) v3(62.04,25.16) v3(63.04,35.16) v3(63.04,34.16) v3(63.04,33.16) v3(63.04,32.16) v3(63.04,31.16) v3(63.04,30.16) v3(63.04,29.16) v3(63.04,28.16) v3(63.04,27.16) v3(63.04,26.16) v3(63.04,25.16) v3(64.04,35.16) v3(64.04,34.16) v3(64.04,33.16) v3(64.04,32.16) v3(64.04,31.16) v3(64.04,30.16) v3(64.04,29.16) v3(64.04,28.16) v3(64.04,27.16) v3(64.04,26.16) v3(65.04,35.16) v3(65.04,34.16) v3(65.04,33.16) v3(65.04,32.16) v3(65.04,31.16) v3(65.04,30.16) v3(65.04,29.16) v3(65.04,28.16) v3(65.04,27.16) v3(66.04,35.16) v3(66.04,34.16) v3(66.04,33.16) v3(66.04,32.16) v3(66.04,31.16) v3(66.04,30.16) v3(66.04,29.16) v3(66.04,28.16) v3(66.04,27.16) v3(67.04,35.16) v3(67.04,34.16) v3(67.04,33.16) v3(67.04,32.16) v3(67.04,31.16) v3(67.04,30.16) v3(67.04,29.16) v3(67.04,28.16) v3(67.04,27.16) v3(68.04,35.16) v3(68.04,34.16) v3(68.04,33.16) v3(68.04,32.16) v3(68.04,31.16) v3(68.04,30.16) v3(68.04,29.16) v3(68.04,28.16) v3(68.04,27.16) v3(69.04,35.16) v3(69.04,34.16) v3(69.04,33.16) v3(69.04,32.16) v3(69.04,31.16) v3(69.04,30.16) v3(69.04,29.16) v3(69.04,28.16) v3(69.04,27.16) v3(70.04,35.16) v3(70.04,34.16) v3(70.04,33.16) v3(70.04,32.16) v3(70.04,31.16) v3(70.04,30.16) v3(70.04,29.16) v3(70.04,28.16) v3(70.04,27.16) v3(71.04,33.16) v3(71.04,32.16) v3(71.04,31.16) v3(71.04,30.16) v3(71.04,29.16) v3(71.04,28.16) v3(71.04,27.16) v3(72.04,32.16) v3(72.04,31.16) v3(72.04,30.16) v3(72.04,29.16) v3(72.04,28.16) v3(72.04,27.16) v3(73.04,32.16) v3(73.04,31.16) v3(73.04,30.16) v3(73.04,29.16) v3(73.04,28.16) v3(73.04,27.16)
V: length 25.3
  TOP w0.457: v3(73.21,22.48) 72.3,23.39 58.17,23.39 56.68,21.89 v1(56.68,21.08)
  BOTTOM w0.305: U1.4 72.14,23.55 72.75,22.93 72.76,22.93 v3(73.21,22.48) 73.29,22.48
  BOTTOM w0.33: R15.1 73.29,22.56
  BOTTOM w0.381: C12.1 R15.1
  BOTTOM w0.76: R11.2 56.68,19.3 v1(56.68,21.08)
VBULK: length 4.9
  BOTTOM w0.305: 85.55,23.95 84.59,24.91 C11.1
  BOTTOM w0.8: R12.1 92.77,17.93
  vias: v3(96.46,22.14) v3(96.46,21.14) v3(97.46,22.14) v3(97.46,21.14) v3(98.46,22.14) v3(98.46,21.14) v3(99.46,23.14) v3(99.46,22.14) v3(99.46,21.14) v3(100.46,25.14) v3(100.46,24.14) v3(100.46,23.14) v3(100.46,22.14) v3(100.46,21.14) v3(101.46,25.14) v3(101.46,24.14) v3(101.46,23.14) v3(101.46,22.14) v3(101.46,21.14) v3(102.46,25.14) v3(102.46,24.14) v3(102.46,23.14) v3(102.46,22.14) v3(102.46,21.14) v3(103.46,25.14) v3(103.46,24.14) v3(103.46,23.14) v3(103.46,22.14) v3(103.46,21.14) v3(104.46,26.14) v3(104.46,25.14) v3(104.46,24.14) v3(104.46,23.14) v3(104.46,22.14) v3(104.46,21.14) v3(105.46,31.14) v3(105.46,30.14) v3(105.46,29.14) v3(105.46,28.14) v3(105.46,27.14) v3(105.46,26.14) v3(105.46,25.14) v3(105.46,24.14) v3(105.46,23.14) v3(105.46,22.14) v3(105.46,21.14) v3(106.46,31.14) v3(106.46,30.14) v3(106.46,29.14) v3(106.46,28.14) v3(106.46,27.14) v3(106.46,26.14) v3(106.46,25.14) v3(106.46,24.14) v3(106.46,23.14) v3(106.46,22.14) v3(106.46,21.14) v3(107.46,31.14) v3(107.46,30.14) v3(107.46,29.14) v3(107.46,28.14) v3(107.46,27.14) v3(107.46,26.14) v3(107.46,25.14) v3(107.46,24.14) v3(107.46,23.14) v3(107.46,22.14) v3(107.46,21.14) v3(108.46,31.14) v3(108.46,30.14) v3(108.46,29.14) v3(108.46,28.14) v3(108.46,27.14) v3(108.46,26.14) v3(108.46,25.14) v3(108.46,24.14) v3(108.46,23.14) v3(108.46,22.14) v3(109.46,31.14) v3(109.46,30.14) v3(109.46,29.14) v3(109.46,28.14) v3(109.46,27.14) v3(109.46,26.14) v3(109.46,25.14) v3(109.46,24.14) v3(109.46,23.14) v3(109.46,22.14)
VDR: length 2.5
  BOTTOM w0.35: U1.12 67.1,22.9 C8.1
VS: length 55.2
  TOP w0.635: v1(74.87,23.38) 74.87,68.24 T1.2
  BOTTOM w0.508: v1(74.87,23.38) 74.92,23.44 R10.1
VSC: length 2.1
  BOTTOM w0.33: U1.1 74.04,24.5 R10.2
Y1: length 21.1
  BOTTOM w0.508: R1.2 28.68,44.51 20.39,36.22 L2.1
Y2: length 37.9
  TOP w0.508: L2.2 9.39,36.22 9.39,41.56 12.05,44.22 35.34,44.22 v3(38.01,41.55)
  BOTTOM w0.508: v3(38.01,41.55) R2.2
N4286456: length 7.4
  TOP w0.45: v1(99.1,28.7) 97.39,28.7 v1(96.1,30)
  BOTTOM w0.4: v1(99.1,28.7) 99.65,29.26 99.65,29.26 99.95,29.56 U2.14
  BOTTOM w0.457: C19.1 v1(96.1,30)
N4286477: length 6.3
  BOTTOM w0.4: R22.1 96.89,28.45 97.29,28.85 97.29,29.34 C17.2 99.33,30.3 99.34,30.31 U2.15
N4286493: length 2.6
  BOTTOM w0.8: R23.2 90.64,32.04 D4.1
N4298336: length 6.1
  BOTTOM w1.5: D6.2 112.83,80.93 114.33,79.43 T2.7
N4342721: length 0.6
  BOTTOM w0.762: 105.76,78.14 R51.1
  BOTTOM w0.8: 106.03,77.99 R51.1
N4344251: length 8.3
  BOTTOM w0.305: R33.1 121.19,31.47 121.24,31.42 Q3.3
  BOTTOM w0.4: R33.1 117.51,31.47 117.17,31.81 115.14,31.81 U2.8
N4347891: length 12.6
  TOP w0.4: v3(118.5,36.22) 118.02,36.7 117.99,36.7 116.54,38.15 v1(116.54,40.51)
  BOTTOM w0.4: v1(116.54,40.51) 116.41,40.65 R30.1 ; U2.5 115.98,34.06 116.98,34.9 C22.1 118.18,34.9 118.5,35.22 v3(118.5,36.22)
N4369156: length 5.6
  BOTTOM w0.4: U3.5 139.48,41.35 140.69,42.56 R37.1 142.4,42.56 142.73,42.23 R36.2
N4369530: length 6.6
  BOTTOM w0.4: R44.1 142.48,44.39 142.47,44.37 C35.1 141.39,44.37 140.66,43.65 140.33,43.65 139.33,42.65 139.33,42.41 139.04,42.12 137.97,42.12 U3.4
N4369660: length 4.5
  BOTTOM w0.381: 136.57,43.91 136.57,43.16 136.87,42.87 137.22,42.87 137.24,42.85 U3.3
  BOTTOM w0.4: R48.2 136.69,45.25 136.57,45.14 136.57,43.91
N4369788: length 2.5
  BOTTOM w0.4: U3.1 137.95,44.4 138.57,45.01 138.57,45.04 138.77,45.24 138.77,45.95 C39.1
N4383576: length 23.1
  TOP w0.4: v3(152.49,38.15) 150.51,36.17 141.87,36.17 v3(140.85,37.18)
  BOTTOM w0.4: U3.9 139.71,38.35 140.37,37.69 140.37,37.67 v3(140.85,37.18) ; R43.2 152.51,44.05 152.49,44.02 v3(152.49,38.15)
N4398139: length 34.4
  TOP w0.45: 148.8,44.98 150.17,43.61 v3(150.17,40.82)
  TOP w0.457: 147.38,63.73 147.38,46.41 148.8,44.98
  BOTTOM w0.4: R40.1 146.74,36.12 147.48,35.38 149.54,35.38 150.17,36.01 v3(150.17,40.82)
  vias: v3(148.57,67.62) v3(148.57,66.62) v3(148.57,65.62) v3(148.57,64.62) v3(148.57,63.62) v3(149.57,67.62) v3(149.57,66.62) v3(149.57,65.62) v3(149.57,64.62) v3(149.57,63.62) v3(150.57,67.62) v3(150.57,66.62) v3(150.57,65.62) v3(150.57,64.62) v3(150.57,63.62) v3(151.57,67.62) v3(151.57,66.62) v3(151.57,65.62) v3(151.57,64.62) v3(151.57,63.62) v3(152.57,67.62) v3(152.57,66.62) v3(152.57,65.62) v3(152.57,64.62) v3(152.57,63.62) v3(153.57,67.62) v3(153.57,66.62) v3(153.57,65.62) v3(153.57,64.62) v3(153.57,63.62)
N4399978: length 17.6
  BOTTOM w0.4: 151.08,46.25 151.08,35.6 149.62,34.14 R45.1
  BOTTOM w0.45: v3(151.37,46.65) 151.16,46.44 151.16,46.33 151.08,46.25
  vias: v3(149.37,50.65) v3(149.37,49.65) v3(149.37,48.65) v3(149.37,47.65) v3(149.37,46.65) v3(150.37,50.65) v3(150.37,49.65) v3(150.37,48.65) v3(150.37,47.65) v3(150.37,46.65) v3(151.37,50.65) v3(151.37,49.65) v3(151.37,48.65) v3(151.37,47.65) v3(152.37,50.65) v3(152.37,49.65) v3(152.37,48.65) v3(152.37,47.65) v3(152.37,46.65) v3(153.37,50.65) v3(153.37,49.65) v3(153.37,48.65) v3(153.37,47.65) v3(153.37,46.65)
N4403571: length 38.8
  TOP w0.4: v3(147.76,37.92) 147.66,37.82 142.6,37.82 v3(142.05,38.38)
  BOTTOM w0.4: v3(142.05,38.38) 141.74,38.68 141.74,38.7 141.34,39.1 U3.8 ; v3(147.76,37.92) 148.53,38.69 148.53,44.62 148.47,44.68 148.47,44.72 146.97,46.22 146.97,59.08 149.54,61.65 R39.2
N4411199: length 2.1
  BOTTOM w0.4: R49.1 136.81,47.66 R48.1
N4411203: length 5.1
  BOTTOM w0.508: R49.2 136.81,52.84 136.84,52.87 C37.1
N4415619: length 1.9
  BOTTOM w0.4: C36.1 143.47,46.74 R44.2
N4462598: length 43.5
  TOP w0.7: v2(144.98,50.34) 141.79,50.34 138.67,47.22 v1(138.67,31.34)
  BOTTOM w0.381: U3.7 137.96,39.84
  BOTTOM w0.4: VR2.2 142.15,30.13 141.82,30.46 Q6.3 139.66,31.34 139.66,31.34 v1(138.67,31.34) 137.88,31.34 137.5,31.73 C33.2 136.71,33.1 136.26,33.54 136.26,39.49 136.63,39.85 U3.7
  BOTTOM w1: v2(144.98,50.34) R41.1
N4490514: length 13.4
  BOTTOM w2.032: 108.14,59.28 111.02,56.4 T2.11
  BOTTOM w2.1: 108.14,59.28 106.05,61.38 C25.1
N11926581: length 18.5
  TOP w0.4: v3(146.69,38.63) 142.94,38.63 142.25,39.32 140.39,39.32 140.29,39.42 140.27,39.42 v3(139.68,40)
  BOTTOM w0.4: v3(139.68,40) 139.09,40.6 U3.6 ; v3(146.69,38.63) 146.83,38.77 146.94,38.77 147.83,39.66 147.83,41.64 146.54,42.93 146.54,45.11 145.84,45.81 R50.1
N12003586: length 3
  BOTTOM w0.305: 123,29.11 Q3.1 123.02,30.12 123.31,30.42 123.83,30.42 123.86,30.44 R32.2
N12130188: length 7.1
  BOTTOM w0.4: U3.11 139.03,36.85 140.56,35.32 142.75,35.32 143.86,34.21 R45.2
N12130239: length 6.5
  BOTTOM w0.4: R40.2 142.84,36.12 142.84,36.12 140.78,36.12 139.28,37.6 U3.10
N12141521:
  vias: v3(102.08,44.82) v3(102.08,43.82) v3(102.08,42.82) v3(102.08,41.82) v3(102.08,40.82) v3(103.08,45.82) v3(103.08,44.82) v3(103.08,43.82) v3(103.08,42.82) v3(103.08,41.82) v3(103.08,40.82) v3(103.08,39.82) v3(104.08,45.82) v3(104.08,44.82) v3(104.08,43.82) v3(104.08,42.82) v3(104.08,41.82) v3(104.08,40.82) v3(104.08,39.82) v3(104.08,38.82) v3(105.08,45.82) v3(105.08,44.82) v3(105.08,43.82) v3(105.08,42.82) v3(105.08,41.82) v3(105.08,40.82) v3(105.08,39.82) v3(105.08,38.82) v3(105.08,37.82) v3(105.08,36.82) v3(105.08,35.82) v3(105.08,34.82) v3(106.08,45.82) v3(106.08,44.82) v3(106.08,43.82) v3(106.08,42.82) v3(106.08,41.82) v3(106.08,40.82) v3(106.08,39.82) v3(106.08,38.82) v3(106.08,37.82) v3(106.08,36.82) v3(106.08,35.82) v3(106.08,34.82) v3(107.08,45.82) v3(107.08,44.82) v3(107.08,43.82) v3(107.08,42.82) v3(107.08,41.82) v3(107.08,40.82) v3(107.08,39.82) v3(107.08,38.82) v3(107.08,37.82) v3(107.08,36.82) v3(107.08,35.82) v3(107.08,34.82) v3(108.08,45.82) v3(108.08,44.82) v3(108.08,43.82) v3(108.08,42.82) v3(108.08,41.82) v3(108.08,40.82) v3(108.08,39.82) v3(108.08,38.82) v3(108.08,37.82) v3(108.08,36.82) v3(108.08,35.82) v3(108.08,34.82) v3(109.08,45.82) v3(109.08,44.82) v3(109.08,43.82) v3(109.08,42.82) v3(109.08,41.82) v3(109.08,40.82) v3(109.08,39.82) v3(109.08,38.82) v3(109.08,37.82) v3(109.08,36.82) v3(109.08,35.82) v3(109.08,34.82) v3(110.08,46.82) v3(110.08,45.82) v3(110.08,44.82) v3(110.08,43.82) v3(110.08,42.82) v3(110.08,41.82) v3(110.08,40.82) v3(110.08,39.82) v3(110.08,38.82) v3(111.08,47.82) v3(111.08,46.82) v3(111.08,45.82) v3(111.08,44.82) v3(111.08,43.82) v3(111.08,42.82) v3(111.08,41.82) v3(111.08,40.82) v3(111.08,39.82) v3(112.08,47.82) v3(112.08,46.82) v3(112.08,45.82) v3(112.08,44.82) v3(113.08,47.82) v3(113.08,46.82) v3(113.08,45.82) v3(114.08,47.82) v3(114.08,46.82) v3(115.08,47.82)
N12150808: length 6.8
  BOTTOM w0.4: R23.1 92.06,34.21 92.87,33.4 92.87,32.79 C18.1 94.07,29.68 94.36,29.38 R22.2
N12190763: length 38.8
  TOP w1: v2(143.08,55.55) 145.55,58.03 145.55,76.33 148.92,79.69 C34.1
  BOTTOM w1: C34.1 154.8,80.21 D7.1 ; R41.2 v2(143.08,55.55)
N12221428: length 2.3
  BOTTOM w0.762: R8.2 61.27,49.27 R6.1
N12221554: length 28.6
  TOP w0.762: v3(53.63,21.13) 53.63,36.02 59.65,42.04 v3(59.65,43.61)
  BOTTOM w0.76: R8.1 61.2,43.61 v3(59.65,43.61)
  BOTTOM w0.762: v3(53.63,21.13) 53.63,19.55 R11.1
N12221692: length 2.5
  BOTTOM w0.7: R13.1 R12.2
N12221812: length 2.5
  BOTTOM w0.7: R14.2 R13.2
N12221868: length 12.4
  BOTTOM w0.305: Q2.1 65.27,18.03 65.27,17.8 ; U1.2 73.4,23.56 74.48,22.48 75.09,22.48 75.55,22.02 75.55,20.72 75.24,20.41 C12.2 73.97,20.41
  BOTTOM w0.35: R15.2 C12.2 74.73,19.36 v3(74.79,19.3) ; R15.2 73.31,20.39 C16.2 ; R15.2 C15.2
  vias: v3(66.96,19.1)
N12222300: length 1.4
  BOTTOM w0.35: C16.1 72.6,17.93 R19.2
N12229995: length 3.2
  BOTTOM w0.8: R31.1 102.96,69.6 D5.2
N12233962: length 1.9
  BOTTOM w0.356: 66.23,16.38 R18.1
  BOTTOM w0.4: Q2.3 64.68,16.38 66.23,16.38
N12234276: length 3.3
  BOTTOM w0.35: R54.1 64.07,18.15 Q2.2
  BOTTOM w0.45: R21.2 63.08,19.37 R54.1
N12240068: length 3.8
  BOTTOM w0.457: R53.2 53.35,48.38 53.45,48.47 R4.2 53.51,48.49 53.51,50.2 ; 53.51,50.2 53.51,50.29 ; 53.51,50.2 Q1.1
N12240080: length 7.4
  BOTTOM w0.457: D2.2 55.52,50.38 55.57,50.43 55.57,50.51 56.46,51.4 56.46,51.78 ; 56.46,51.78 56.47,51.79 RL1.1 ; 56.46,51.78 55.66,52.58 52.66,52.58 Q1.3
N12240868: length 2.3
  BOTTOM w0.457: D2.1 56.18,47.81 R3.2
N12267959: length 9.4
  BOTTOM w0.4: C40.2 151.44,31.8 150.27,32.97 147.15,32.97 146.26,32.08 R5.1 145.98,32.28 Q6.1
N12332190: length 2.8
  BOTTOM w0.4: R25.1 112.45,20.67 R24.2
N12332212: length 2.6
  BOTTOM w0.4: R26.1 114.59,23.47 114.59,23.47 R25.2
N12355111: length 3
  BOTTOM w0.4: R35.2 148.65,28.42 VR2.1
N12418022: length 17.5
  TOP w0.381: v1(118.17,22.73) 118.17,25.75 115.12,28.8 v3(115.12,36.3)
  BOTTOM w0.4: v3(115.12,36.3) 115.11,36.31 U2.2
  BOTTOM w0.45: v1(118.17,22.73) 118.15,22.71 D9.2

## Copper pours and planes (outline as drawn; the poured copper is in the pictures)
+24V on TOP: 137.78,0.41 137.65,0.53 137.65,2.49 137.73,2.56 156.78,2.56 157.11,2.89 157.11,19.33 160.36,22.58 160.36,34.24 163.58,37.46 163.58,65.66 159.22,70.03 159.22,75.11 163.94,79.83 166.43,79.83 167.57,78.69 167.57,0.99 166.99,0.41
+24V on BOTTOM: 157.11,0.66 157.11,19.33 160.36,22.58 160.36,34.23 163.58,37.46 163.58,65.66 160.56,68.68 160.56,68.68 159.22,70.03 159.22,75.11 163.94,79.83 166.43,79.83 167.52,78.74 167.52,28.81 167.57,28.75 167.57,0.99 166.99,0.41 157.36,0.41
GND on BOTTOM (solid shape): 155.81,64.46 154.9,64.46 154.9,67.39 155.81,67.39
GND on BOTTOM (solid shape): 155.86,47.8 154.95,47.8 154.95,50.72 155.86,50.72
GND on TOP: 162.77,65.46 162.77,40.23 160.46,37.92 155.43,37.92 154.81,38.54 154.81,50.82 156.86,52.87 156.86,58.26 154.77,60.36 154.77,67.52 155.98,68.73 159.5,68.73
GND on TOP: 140.62,31.04 140.62,27.63 141.01,27.25 150,27.25 150.3,27.56 150.3,34.57 150.12,34.75 140.5,34.75 140.01,35.23 139.43,35.23 139.3,35.1 139.3,32.36
GND on TOP: 138.06,4.47 138.06,22.48 140.34,24.76 146.03,24.76 147.61,26.34 152.05,26.34 152.71,27 152.71,33.65 153.53,34.47 158.61,34.47 159.47,33.6 159.47,23.06 156.19,19.79 156.19,4.09 155.84,3.73 138.8,3.73
GND on BOTTOM: 142.55,34.8 142.83,34.52 142.83,33.5 141.82,32.49 138.69,32.49 138.44,32.74 138.44,34.21 138.16,34.49 137.2,34.49 136.94,34.75 136.94,36.04 137.2,36.3 138.85,36.3 140.34,34.8
GND on BOTTOM: 137.78,0.41 137.65,0.53 137.65,2.49 138.06,2.89 138.06,22.48 140.34,24.76 146.03,24.76 147.61,26.34 152.05,26.34 152.71,27 152.71,33.66 154.64,35.59 154.72,35.67 154.72,40.48 157.37,43.13 158.07,43.82 158.07,47.22 157.59,47.7 155.05,47.7 155.03,47.72 155.03,50.8 157.06,52.83 157.06,58.02 158.45,59.41 158.45,63.75 157.84,64.36 154.99,64.36 154.97,64.39 154.97,67.48 156.19,68.71 159.53,68.71 162.77,65.47 162.79,65.45 162.79,37.62 162.77,37.6 159.47,34.35 159.47,28.65 159.47,28.65 159.47,23.06 156.19,19.79 156.19,0.66 155.94,0.41
GND on BOTTOM: 141.06,38.58 141.54,38.1 142.17,38.1 142.33,38.25 142.33,39.04 142.38,39.09 145.96,39.09 147.56,37.49 148.19,37.49 148.9,38.2 149.23,38.2 149.46,37.97 149.46,36.14 149.21,35.89 147.69,35.89 146.47,37.11 142.86,37.11 142.38,36.63 141.74,36.63 141.56,36.8 141.56,37.21 140.6,38.18 140.6,38.45 140.73,38.58
VCC on BOTTOM: 66,23.81 65.99,23.8 64.29,23.8 64.02,23.53 62.3,21.81 59.22,21.81 59.19,21.84 59.19,22.61 59.22,22.63 62.09,22.63 64.7,25.24 66,25.24
D1 on BOTTOM: 66.63,36.57 66.63,38.02 65.67,38.02 65.67,36.57
D2 on BOTTOM: 68.54,36.57 68.54,38.02 67.44,39.12 66.7,39.12 66.7,38.64 66.72,38.62 66.92,38.62 67.57,37.97 67.57,36.57
G2 on BOTTOM: 60.94,21.26 62.37,21.26 64.52,23.41 64.6,23.49 66.17,23.49 66.32,23.64 66.32,25.23 66.61,25.23 66.61,23.44 65.66,22.49 65.66,21.37 65.68,21.36 65.68,20.54 65.67,20.54 65.67,20.45 65.52,20.29 62.8,20.29 62.44,19.94 61,19.94 60.79,20.14 60.79,21.11
GP on TOP: 122.16,38.51 121.29,39.37 120.02,39.37 118.58,37.92 118.58,36.98 119.36,36.19 119.36,33.07 118.83,32.54 118.83,28.42 119.1,28.16 120.1,28.16 122.16,30.21
GP on BOTTOM: 52.21,50.88 49.77,50.88 49.29,50.39 49.29,44.88 50.23,43.94 51.95,43.94 52,43.99 52,45.67 50.71,46.96 50.71,49.4 50.94,49.63 52.16,49.63 52.28,49.76 52.28,50.8
GP on BOTTOM: 121.73,41.07 125.84,41.07 125.94,40.97 125.94,38.45 125.81,38.33 123.88,38.33 123.88,38.33 121.81,38.33 121.01,37.52 121.01,35.32 120.56,34.87 119.44,34.87 119.01,35.31 119.01,35.53 118.68,35.53 118.58,35.64 118.58,37.91
GP on BOTTOM: 120.02,30.56 118.75,30.56 118.53,30.78 115.15,30.78 114.87,30.5 114.77,30.5 114.77,30.1 114.92,30.1 115.15,29.87 118.27,29.87 118.35,29.79 118.35,28.65 119.42,27.58 119.42,25.35 119.67,25.09 121.52,25.09 121.73,25.3 121.73,29.9 121.62,30 120.58,30
GSB on TOP: 148.22,40.64 147.96,40.39 146.47,40.39 146.03,39.95 146.03,39.47 145.83,39.27 142.94,39.27 142.38,39.83 140.6,39.83 139.3,41.12 139.3,46.94 141.64,49.28 146.19,49.28 146.67,48.79 146.67,45.97 148.22,44.42
GSB on BOTTOM: 137.78,43.38 137.75,43.41 137.75,43.79 137.78,43.81 139.13,43.81 139.19,43.88 139.19,44.72 140.14,45.67 140.14,47.12 138.64,48.61 138.64,58.6 139.27,59.22 143.71,59.22 144.97,60.48 144.97,64.49 143.88,65.58 141.49,65.58 140.32,66.75 140.32,68.05 141.56,69.29 144.54,69.29 146.14,67.69 146.14,57.48 145.63,56.97 142.45,56.97 141.82,56.34 141.82,54.96 143.27,53.52 143.27,49.83 142.68,49.25 142.68,47.09 142.43,46.84 142.43,45.64 142.06,45.27 141.07,45.27 140.47,44.68 140.47,44.5 139.35,43.38
L on BOTTOM (solid shape): 75.47,47.83 72.83,47.83 72.83,51.11 75.47,51.11
L on BOTTOM: 72.65,62.99 75.03,62.99 75.47,62.55 75.47,37.21 74.83,36.57 73.61,36.57 73.61,41.6 71.38,43.83 71.38,51.43 66.83,55.98 66.83,57.5 67.8,58.47 71.13,58.47 72.35,59.69 72.35,62.69
LINE1 on TOP: 8.11,11.91 8.85,11.18 11.49,11.18 11.64,11.02 11.64,10.79 11.59,10.74 7.73,10.74 7.17,11.3 5.28,11.3 4.57,10.59 4.57,9.61 5.24,8.94 9.64,8.94 10.8,7.77 16.11,7.77 16.92,8.67 16.92,9.88 12.65,14.15 8.95,14.15 8.11,13.31
LINE1 on BOTTOM: 8.11,11.91 8.85,11.18 11.49,11.18 11.64,11.02 11.64,10.79 11.59,10.74 7.73,10.74 7.17,11.3 5.28,11.3 4.57,10.59 4.57,9.61 5.24,8.94 9.64,8.94 10.8,7.77 16.11,7.77 16.92,8.67 16.92,9.88 12.65,14.15 8.95,14.15 8.11,13.31
NEUTRAL1 on TOP: 19.14,12.01 19.14,12.83 19.15,12.84 19.15,13.4 19.9,14.15 21.35,14.15 25.23,10.26 25.23,6.91 27.04,5.1 29.35,5.1 31.89,2.56 129.52,2.56 129.6,2.49 129.6,0.51 129.5,0.41 27.01,0.41 22.31,5.1 22.31,7.9 22.3,7.91 22.3,8.85
NEUTRAL1 on BOTTOM: 19.14,12.01 19.14,12.83 19.15,12.84 19.15,13.4 19.87,14.12 21.37,14.12 25.23,10.26 25.23,6.91 27.04,5.1 29.35,5.1 31.89,2.56 129.52,2.56 129.6,2.49 129.6,0.51 129.5,0.41 27.01,0.41 22.31,5.1 22.31,8.84
REF on BOTTOM: 67.56,25.24 67.56,23.79 68.53,23.79 68.53,25.24
RTN on TOP: 46.47,61.14 56.47,61.14 57.49,60.12 57.49,55.9 56.83,55.24 49.84,55.24 48.65,54.05 48.65,50.37 48.19,49.91 45.58,49.91 45.09,50.39 45.09,59.77
RTN on TOP: 68.41,42.34 70.59,42.34 72.21,43.96 72.21,63.64 66.98,68.87 66.98,70.22 67.84,71.08 69.12,71.08 74.14,66.06 74.14,24.32 73.72,23.9 55.51,23.9 54.9,24.51 54.9,34.21 63.02,42.34 68.41,42.34
RTN on TOP: 83.4,32.92 83.4,42.47 84.69,43.76 84.69,49.66 83.47,50.88 78.19,50.88 77.66,51.41 77.66,69.06 71.54,75.18 71.54,78.16 72.07,78.69 94.95,78.69 95.87,77.77 95.87,47.32 89.27,40.72 89.27,35.94 87.77,34.44 87.77,32.92 86.52,31.67 84.64,31.67
RTN on TOP: 36.59,35.51 36.24,35.17 36.24,17.74 36.81,17.17 48.6,17.17 49.33,17.9 49.33,34.54 48.37,35.51
RTN on BOTTOM: 36.81,17.17 36.24,17.74 36.24,35.04 36.71,35.51 68.82,35.51 69.45,36.14 69.45,38.66 67.98,40.13 48.79,40.13 45.1,43.82 45.1,52.13 45.09,52.15 45.09,59.76 46.46,61.12 56.48,61.12 56.89,60.72 56.89,60.71 57.49,60.1 57.49,55.9 56.83,55.25 49.84,55.25 48.65,54.05 48.65,44.78 51.19,42.24 68.43,42.24 70.43,40.24 70.43,34.94 72.32,33.04 77.12,33.04 78.32,34.24 78.32,34.27 78.86,34.82 78.86,40.8 79.6,41.53 83.46,41.53 83.82,41.89 87.8,45.87 91.07,45.87 96.83,51.63 106.97,51.63 107.71,50.9 107.71,48.64 107.12,48.06 101.15,48.06 99.35,46.25 99.35,39.82 101.88,37.29 101.88,36.82 90.23,36.82 87.75,34.35 87.75,28.87 87.23,28.35 79.6,28.35 76.94,25.68 64.56,25.68 62.39,23.51 58.24,23.51 58.23,23.49 53.35,23.49 50.53,20.67 50.53,17.6 50.1,17.17
VBULK on TOP: 81.11,43.74 81.11,28.73 83.85,25.99 87.59,25.99 87.61,25.96 87.61,23.86 88.51,22.96 94.46,22.96 95.14,23.64 95.14,25.92 95.53,26.31 101.62,26.31 101.99,26.68 101.99,31.32 102.16,31.5 110.53,31.5 110.7,31.33 110.7,21.49 109.85,20.64 79.92,20.64 78.86,21.7 78.86,47.59 79.13,47.85 82.18,47.85 82.18,44.8
VBULK on BOTTOM: 95.25,75.49 95.9,74.83 95.9,54.59 90.54,49.22 86.63,49.22 82.18,44.78 81.85,44.78 81.83,44.79 78.97,44.79 78.97,44.81 78.59,45.19 78.59,74.98 79.1,75.49
VBULK on BOTTOM: 91.98,16.76 91.8,16.94 91.8,20.09 91.5,20.4 80.16,20.4 79.9,20.66 79.9,25.96 79.93,25.92 80.87,25.92 80.94,25.99 87.54,25.99 87.59,25.94 87.59,22.76 88.2,22.15 94.37,22.15 95.13,22.91 95.13,25.91 95.54,26.31 103.36,26.31 104.96,27.91 104.96,31.29 105.16,31.5 109.89,31.5 110.22,31.17 110.22,19.28 107.7,16.76
VRECT on TOP: 37.55,75.87 56.85,75.87 57.85,74.88 57.85,66.8 57.57,66.52 57.03,66.52 50.86,72.69 37.7,72.69 37.55,72.85
VRECT on TOP: 63.51,69.24 70.14,62.61 70.14,61.26 69.15,60.27 66.33,60.27 64.32,58.27 64.32,54.61 69.2,49.73 69.2,45.69 68.18,44.68 66.96,44.68 65.97,45.67 65.97,48.49 63.51,50.95
VRECT on BOTTOM: 60.28,52.04 60.28,63.27 50.86,72.69 37.7,72.69 37.55,72.85 37.55,75.87 56.88,75.87 70.12,62.62 70.14,62.61 70.14,61.25 69.17,60.27 66.33,60.27 64.32,58.27 64.32,54.61 69.18,49.75 69.18,45.69 68.17,44.68 66.96,44.68 65.97,45.67 65.97,48.48 62.66,51.8 60.52,51.8
Y1 on BOTTOM (solid shape): 21.39,42.88 19.39,42.88 19.39,45.88 19.89,44.88 20.39,45.88 20.89,44.88 21.39,45.88
Y1 on TOP: 19.19,24 20.98,25.8 20.98,30.7 18.67,33.01 18.67,37.08 19.6,38.01 21.17,38.01 22.13,37.06 22.13,34.46 23.78,32.81 23.78,24.28 23.31,23.81 37.09,10.03 120,10.03 126.63,16.66 129.6,16.66 130.32,15.94 130.32,13.93 123,6.6 35.29,6.6 19.19,22.71
Y1 on BOTTOM: 23.78,32.81 22.13,34.46 22.13,43.03 21.4,43.76 19.39,43.76 18.67,43.04 18.67,33.01 20.98,30.7 20.98,25.77 19.21,24 19.21,22.64 20.18,21.67 21.17,21.67 23.78,24.28
Y2 on BOTTOM (solid shape): 10.35,42.85 8.35,42.85 8.35,45.85 8.85,44.85 9.35,45.85 9.85,44.85 10.35,45.85
Y2 on TOP: 6,32.82 7.66,34.47 7.66,37.01 8.65,38 10.09,38 11.11,36.98 11.11,33.02 8.8,30.71 8.8,27.23 8.81,27.22 8.81,26.25 11.24,23.82 11.24,22.55 10.35,21.67 9.03,21.67 6,24.69
Y2 on BOTTOM: 24.98,16.91 13.78,16.91 6,24.69 6,32.82 7.66,34.47 7.66,43.05 8.37,43.76 10.35,43.76 11.11,43 11.11,33.02 8.8,30.71 8.8,26.29 15.68,19.4 27.75,19.4 37.12,10.03 128.79,10.03 130.24,8.58 130.24,7.29 129.55,6.6 35.29,6.6
N4285050 on BOTTOM: 101.84,31.04 100.01,31.04 99.25,31.8 97.63,31.8 97.63,32.22 96.76,33.09 93.55,33.09 93.55,34.35 101.64,34.35 101.89,34.1 101.89,31.09
N4342721 on BOTTOM: 104.81,82.27 107.02,82.27 107.4,81.89 107.4,77.32 107.05,76.96 107.05,73.3 106.77,73.02 106.77,71.3 106.54,71.07 105.37,71.07 105.22,71.22 105.22,73.51 104.25,74.47 102.27,74.47 102.14,74.6 102.14,76 102.35,76.2 103.57,76.2 104.71,77.34 104.71,82.17
N4345605 on BOTTOM: 113.07,38.3 113.07,36.93 113.14,36.85 116.01,36.85 116.54,36.32 117.71,36.32 118.12,36.73 118.12,37.9 119.95,39.72 119.95,43.18 119.49,43.64 118.86,43.64 118.42,43.2 118.42,40.06 117.1,38.73 113.47,38.73 113.05,38.32
N4398139 on BOTTOM (solid shape): 153.85,63.19 149.82,63.19 149.82,67.41 153.85,67.41
